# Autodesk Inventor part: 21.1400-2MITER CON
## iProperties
Created: 2006-12
Part Number: 21.1400-2MITER CON
Document SubType Name: Modeling
Designer: Andy Moles
Material: Steel
Mass: 22.541 g
Surface Area: 15.9808 cm^2
Volume: 2.87147 cm^3
Density: 7.85 g/cm^3
Author: Andy Moles
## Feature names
1. Extrusion1
2. Revolution1
3. Extrusion2
4. Extrusion3
5. Chamfer1
6. Hole2
7. Chamfer2
